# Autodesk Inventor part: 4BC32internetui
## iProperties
Created: 2010-11
Part Number: 4BC32internetui
Document SubType Name: Modeling
Designer: Darius
Author: Darius
Translation Standard: STEP AP203
File Name: 4BC32.STEP
Preprocessor: SolidWorks 2003240
Postprocessor: Build: 272, Release: 10 SP3a - Date: Thu 12/15/2005
Sent Units: MILLIMETERS
Uncertainty: 1e-05
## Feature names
1. Base1
